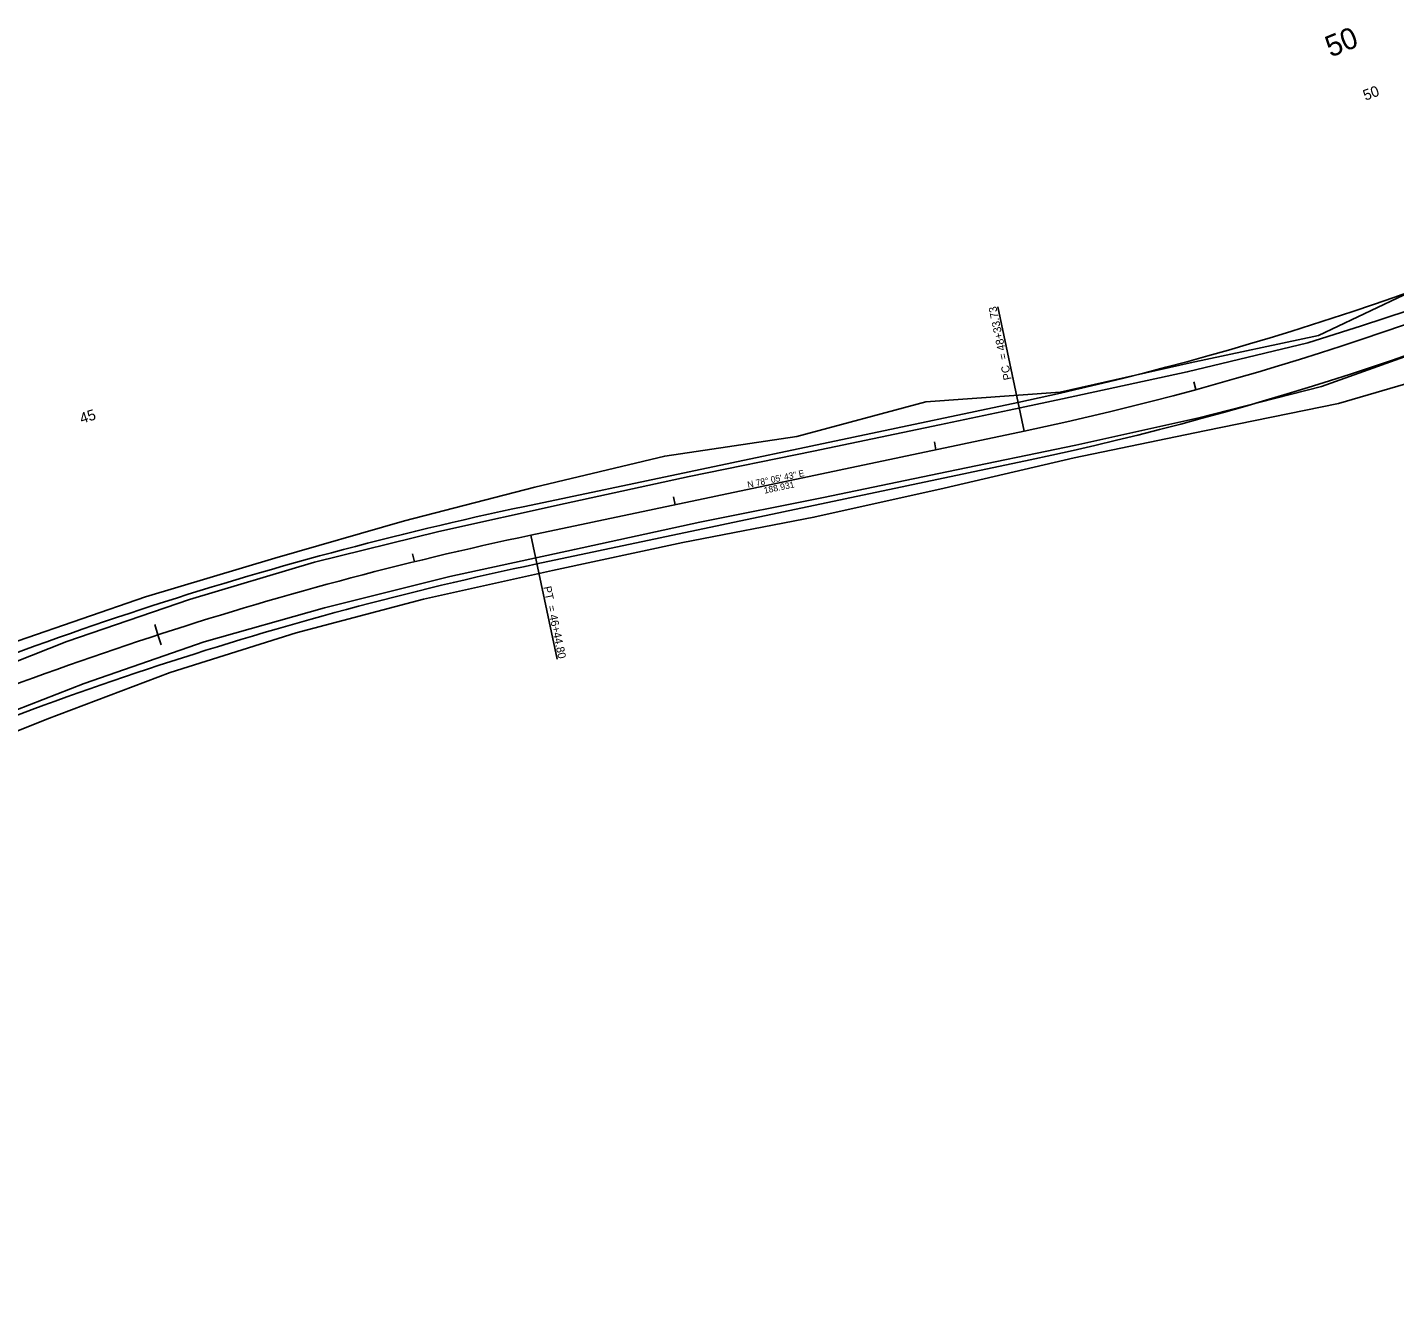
# Model space of a CAD drawing. Extents: x 1965724 to 1970316, y 1117080 to 1118173.
# Drawn here: x 1966236 to 1966749, y 1117080 to 1117558 of the extents above; entities that cross this region are included whole.
import ezdxf

# ---------------------------------------------------------------- set-up
doc = ezdxf.new("R2010")
doc.units = 0
for name, color, linetype in [('RD_EX_Road', 7, 'Continuous'), ('RD_EX_RW', 7, 'Continuous'), ('RD_HC_CL', 7, 'Continuous'), ('RD_HC_Data', 7, 'Continuous'), ('RD_HC_TX_Rel_Sta50', 7, 'Continuous'), ('RD_HC_TX_Sta20', 7, 'Continuous'), ('RD_PD_Final_TrvlWay', 7, 'Continuous')]:
    doc.layers.add(name, color=color, linetype=linetype)

msp = doc.modelspace()

# ---------------------------------------------------------------- linework, layer by layer
at = {"layer": 'RD_EX_Road'}
for points in [[(1965723.84, 1117094.48), (1965813.3, 1117133.71), (1965900.46, 1117173.51), (1965988.47, 1117213.41), (1966031.82, 1117232.96), (1966074.66, 1117252.15), (1966117.78, 1117271.58), (1966161.06, 1117290.48), (1966205.41, 1117309.23), (1966251.25, 1117327.39), (1966297.25, 1117343.1), (1966344.08, 1117357.04), (1966390.78, 1117368.56), (1966438.12, 1117379.08), (1966484.55, 1117389.13), (1966531.2, 1117398.73), (1966578.39, 1117408.59), (1966604.53, 1117414.06), (1966624.54, 1117418.32), (1966671.32, 1117428.35), (1966716.51, 1117439.32), (1966736.6, 1117445.59), (1966754.13, 1117451.44)], [(1965729.99, 1117080.3), (1965819.77, 1117119.13), (1965907.74, 1117159.31), (1965995.36, 1117199.04), (1966039.27, 1117218.5), (1966081.24, 1117237.15), (1966124.67, 1117256.55), (1966167.66, 1117275.55), (1966211.47, 1117293.63), (1966257.79, 1117311.58), (1966302.7, 1117327.21), (1966347.9, 1117339.98), (1966394.81, 1117351.64), (1966441.56, 1117361.87), (1966488.62, 1117372.06), (1966534.91, 1117381.34), (1966581.23, 1117390.95), (1966629.53, 1117400.95), (1966675.63, 1117411.11), (1966721.68, 1117422.85), (1966766.8, 1117438.97), (1966775.75, 1117440.57)]]:
    msp.add_lwpolyline(points, dxfattribs=at)
at = {"layer": 'RD_EX_RW'}
for points in [[(1966377.84, 1117372.53), (1966426.78, 1117385.22), (1966475.43, 1117396.85), (1966524.97, 1117404.23), (1966573.34, 1117417.2), (1966623.68, 1117420.76), (1966672.45, 1117431.82), (1966720.52, 1117441.96), (1966764.73, 1117463)], [(1965790.81, 1117092.42), (1965879.47, 1117136.24), (1965925.17, 1117156.52), (1965970.94, 1117176.66), (1966016.61, 1117197.02), (1966061.92, 1117218.16), (1966106.86, 1117240.14), (1966152.39, 1117260.77), (1966197.92, 1117279.91), (1966243.77, 1117298.28), (1966290.04, 1117315.7), (1966337.21, 1117330.57), (1966385.03, 1117343.22), (1966433.37, 1117353.95), (1966482.26, 1117364.43), (1966531.37, 1117373.89), (1966580.17, 1117384.77), (1966628.88, 1117396.12), (1966677.82, 1117406.34), (1966728, 1117416.5), (1966777.64, 1117431.05)], [(1966139.22, 1117289.89), (1966186.05, 1117308.94), (1966233.02, 1117327.61), (1966280.8, 1117344.12), (1966329.24, 1117358.54), (1966377.84, 1117372.53)]]:
    msp.add_lwpolyline(points, dxfattribs=at)
at = {"layer": 'RD_HC_CL'}
msp.add_line((1966425.26, 1117367.21), (1966610.12, 1117406.19), dxfattribs=at)
for centre, radius, start, end in [((1966373.74, 1118527.46), 1145.91, 281.90472, 295.04633), ((1966705.48, 1116038.04), 1358.39, 101.90472, 114.38256)]:
    msp.add_arc(centre, radius, start, end, dxfattribs=at)
at = {"layer": 'RD_HC_Data'}
for p, q in [((1966610.12, 1117406.19), (1966600.3, 1117452.79)), ((1966674.54, 1117421.73), (1966673.75, 1117424.62)), ((1966577.12, 1117399.23), (1966576.51, 1117402.17)), ((1966479.28, 1117378.6), (1966478.66, 1117381.54)), ((1966425.26, 1117367.21), (1966435.07, 1117320.67)), ((1966381.59, 1117357.25), (1966380.87, 1117360.17)), ((1966285.44, 1117329.86), (1966284.2, 1117333.66)), ((1966285.44, 1117329.86), (1966286.67, 1117326.05))]:
    msp.add_line(p, q, dxfattribs=at)
at = {"layer": 'RD_PD_Final_TrvlWay'}
for p, q in [((1966422.99, 1117377.98), (1966607.86, 1117416.95)), ((1966427.53, 1117356.45), (1966612.39, 1117395.42))]:
    msp.add_line(p, q, dxfattribs=at)
for centre, radius, start, end in [((1966373.74, 1118527.46), 1134.91, 281.90472, 295.04633), ((1966373.74, 1118527.46), 1156.91, 281.90472, 295.04633), ((1966705.48, 1116038.04), 1369.39, 101.90472, 114.38256), ((1966705.48, 1116038.04), 1347.39, 101.90472, 114.38256)]:
    msp.add_arc(centre, radius, start, end, dxfattribs=at)

# ---------------------------------------------------------------- texts
at = {"layer": 'RD_HC_Data'}
for s, height, rotation, p in [('PC  = 48+33.73', 3, 101.9047, (1966605.51, 1117425.65)), ('N 78%%d 05\' 43" E', 2.4, 11.9047, (1966506.67, 1117384.89)), ('188.931', 2.4, 11.9047, (1966512.87, 1117382.72)), ('PT  = 46+44.80', 3, 281.9047, (1966429.88, 1117347.75))]:
    msp.add_text(s, height=height, rotation=rotation, dxfattribs=at).set_placement(p)
at = {"layer": 'RD_HC_TX_Rel_Sta50'}
msp.add_text('50', height=8, rotation=21.9959, dxfattribs=at).set_placement((1966725.07, 1117546.15))
at = {"layer": 'RD_HC_TX_Sta20'}
for s, rotation, p in [('50', 20.2184, (1966738.1, 1117530)), ('45', 18.0122, (1966256.86, 1117408.89))]:
    msp.add_text(s, height=4, rotation=rotation, dxfattribs=at).set_placement(p)

doc.saveas('drawing.dxf')
